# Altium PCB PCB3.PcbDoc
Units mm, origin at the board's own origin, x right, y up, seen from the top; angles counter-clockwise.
Board outline 98.68 x 60.83 mm, 2 copper layers (Top Layer, Bottom Layer); 30 components, 23 nets, 144 pads, 7 vias.
Unrouted connection lines stored in the file: 1.
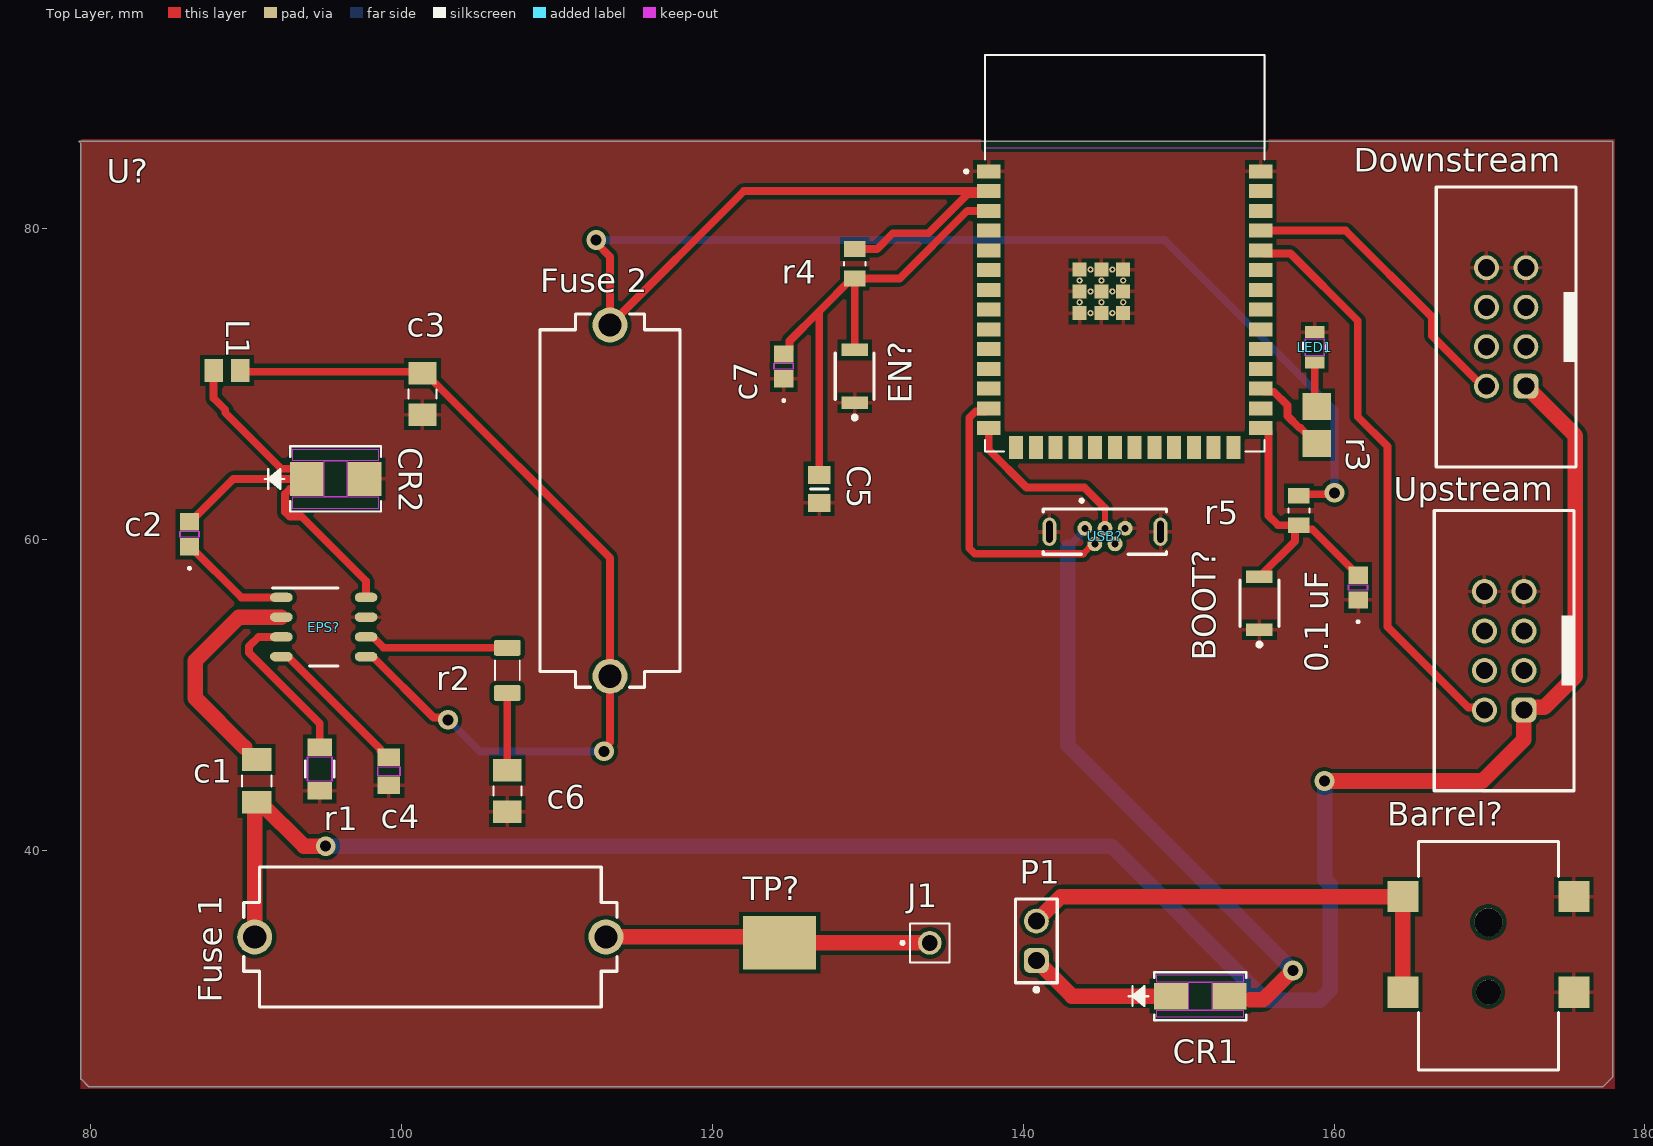
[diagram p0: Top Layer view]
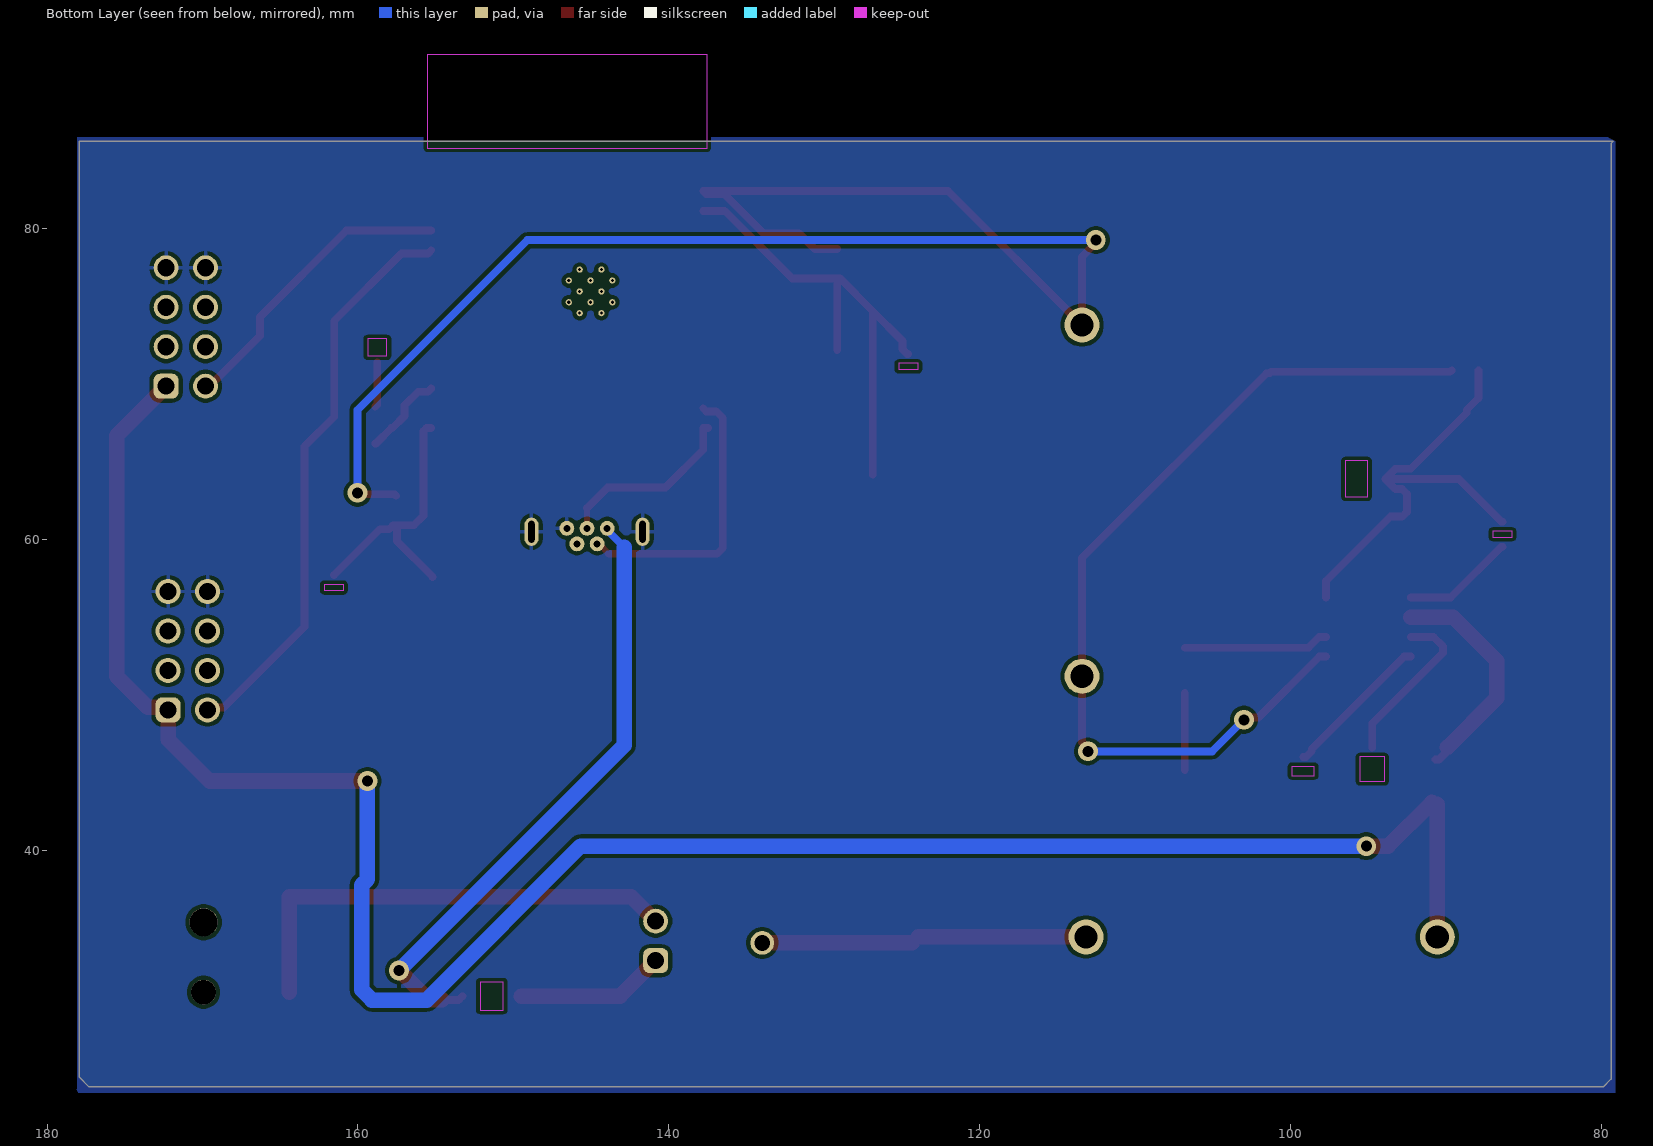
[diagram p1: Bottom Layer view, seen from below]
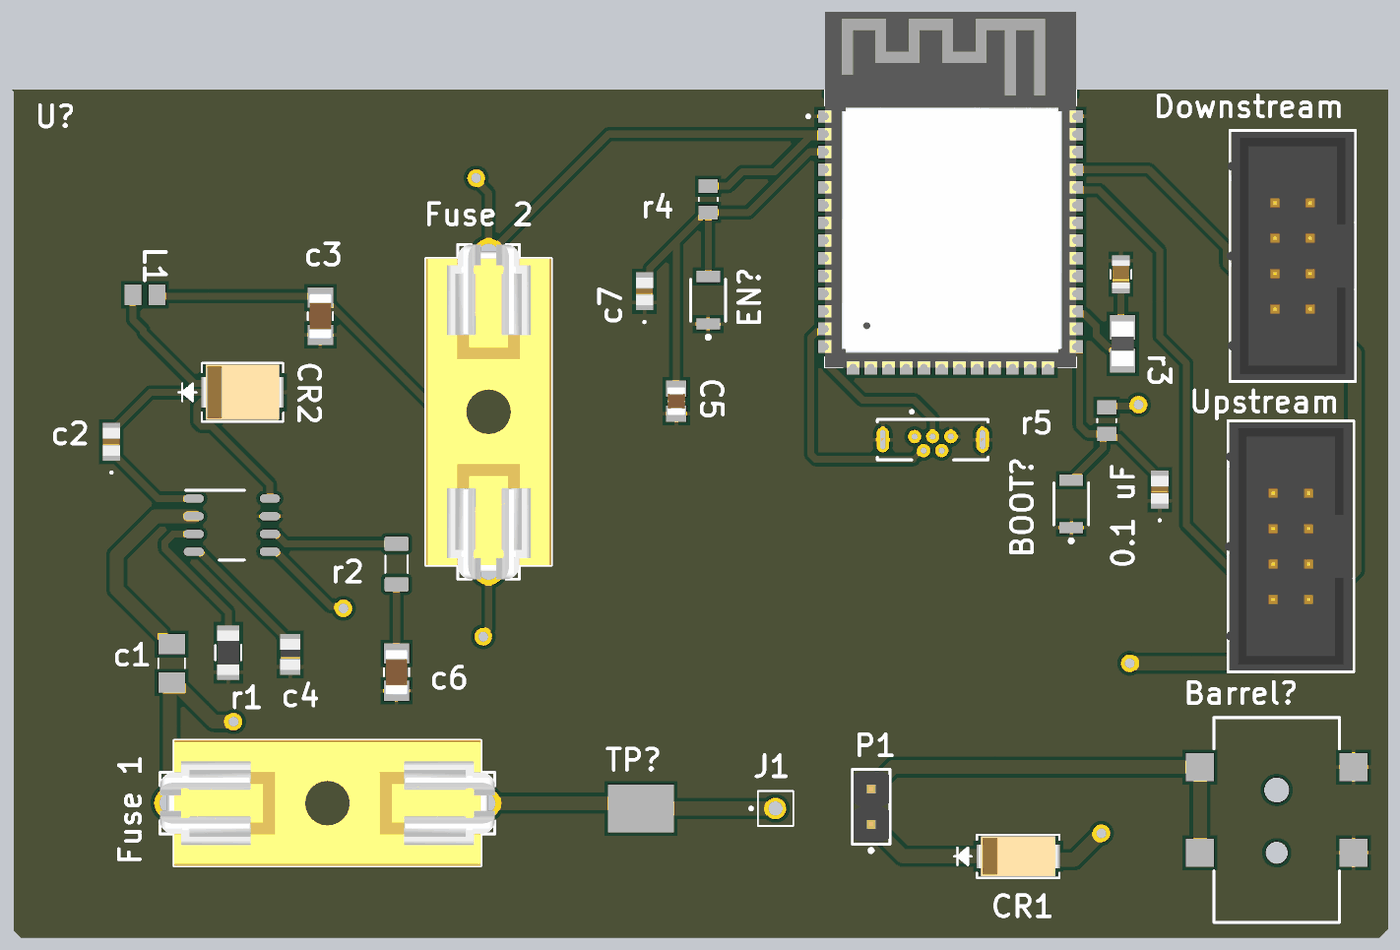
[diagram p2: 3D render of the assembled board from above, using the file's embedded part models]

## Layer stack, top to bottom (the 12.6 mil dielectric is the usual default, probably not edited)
Top Solder: solder mask 0.0102, Solder Resist, Dk 3.5
Top Layer: signal copper 0.0356
Dielectric 1: dielectric 0.32, FR-4, Dk 4.8
Bottom Layer: signal copper 0.0356
Bottom Solder: solder mask 0.0102, Solder Resist, Dk 3.5

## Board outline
79.375,25.273 79.883,24.765 177.292,24.765 177.927,25.4 177.927,85.598 79.248,85.598 79.375,85.471

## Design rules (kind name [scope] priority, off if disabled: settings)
Clearance [All] p1: gap=0.254 ignorepadtopadclearanceinfootprint=TRUE
MinimumSolderMaskSliver [All] p1: minsoldermaskwidth=0.1
PolygonConnect [All] p1: connectstyle=Relief reliefconductorwidth=0.254 reliefentries=4 polygonreliefangle="90 Angle" airgapwidth=0.254
RoutingVias [All] p1: holewidth=0.711 width=1.27 viastyle="Through Hole" minholewidth=0.711 minwidth=1.27 maxholewidth=0.711 maxwidth=1.27
SilkToSolderMaskClearance [IsText] p1: minsilkscreentomaskgap=0.254 clearancetoexposedcopper=TRUE
SolderMaskExpansion [All] p1: expansion=0.05 istentingtop=FALSE
SupplyNets "Schematic Supply Nets" [InNet('GND')] p1: voltage=0.000
Width [All] p1: maxlimit=1 minlimit=0.254 preferedwidth=0.5 minimp=50.000000 maximp=50.000000 favimp=50.000000
28 further rules are at their usual default settings.

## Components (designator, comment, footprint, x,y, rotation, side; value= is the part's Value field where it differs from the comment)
"0.1 uF" "KGM21NR71H104KT" CAP_KGM21_KAV 161.544,56.896 r90 top
Barrel? "DCJ200-05-A-XX-X_REVA" GCT_DCJ200-05-A-XX-X_REVA 169.926,33.211 r0 top
BOOT? "B3U-1000P" OMRON-B3U-1000_V 155.194,55.88 r90 top
c1 "GRJ31CR61E106KE11L" CAPC3216X190N 90.678,44.45 r90 top value=10µF
c2 "KGM21NR71H104KT" CAP_KGM21_KAV 86.36,60.325 r90 top
c3 "C3216X7S0J336M160AC" CAPC3216X180N 101.346,69.342 r90 top value=33µF
c4 "08055C103KAT2A" CAP_X7R_0805_AVX 99.187,45.085 r90 top
C5 "CL21B105KBFNNNE" CAPC2012X140N 126.873,63.246 r270 top value=1µF
c6 "C3216C0G2J222J115AA" CAPC3216X130N 106.807,43.815 r90 top value=2.2nF
c7 "KGM21NR71H104KT" CAP_KGM21_KAV 124.587,71.12 r90 top
CR1 "S1MTR" SMA_SDS 151.384,30.607 r0 top
CR2 "B240-13-F" SMB_DIO 95.758,63.881 r0 top
Downstream "61200821621" 61200821621 171.069,73.66 r90 top
EN? "B3U-1000P" OMRON-B3U-1000_V 129.159,70.485 r90 top
EPS? "TPS5403DR" D0008A_N 94.996,54.356 r0 top
"Fuse 1" "696101000002" 696101000002 101.854,34.417 r180 top
"Fuse 2" "696101000002" 696101000002 113.411,62.484 r90 top
J1 "PH1-01-UA" ADAM-TECH_PH1-01-UA 133.985,34.036 r0 top
L1 "MLF2012C820MT000" INDC2012X145N 88.773,70.866 r0 top value=82µH
LED1 "LSM0805452V" LED_05452V_VCC 158.75,72.352 r90 top
P1 "61300211121" 61300211121 140.843,34.163 r90 top
r1 "RC1206FR-0728KL" RC1206N_YAG 94.742,45.212 r270 top
r2 "RC1206FR-1047KL" RESC3116X65N 106.807,51.562 r90 top value=47k
r3 "HRG3216P-68R0-D-T1" RESC3216X55N 158.877,67.357 r270 top value=68
r4 "RMCF0805FT10K0" RESC2012X65N 129.159,77.724 r90 top value=10k
r5 "RMCF0805FT10K0" RESC2012X65N 157.734,61.849 r90 top value=10k
TP? "5018" TP470X343 124.333,34.036 r0 top
U? "ESP32-S3-WROOM-1-N8R8" XCVR_ESP32S3WROOM1N8R8 146.531,78.409 r0 top
Upstream "61200821621" 61200821621 170.942,52.832 r90 top
USB? "USB3131-30-0230-A_REVB" GCT_USB3131-30-0230-A_REVB 145.258,60.486 r0 top

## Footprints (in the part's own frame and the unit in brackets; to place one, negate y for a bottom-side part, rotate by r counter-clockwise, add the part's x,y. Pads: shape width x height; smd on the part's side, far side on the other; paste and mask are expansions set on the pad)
61200821621 [mm] "8 pins, straight, gold plating"
  rrect50% 1.6x1.6 hole 1.1: 1(-3.81,-1.27)
  round 1.6 hole 1.1: 2(-3.81,1.27) 3(-1.27,-1.27) 4(-1.27,1.27) 5(1.27,-1.27) 6(1.27,1.27) 7(3.81,-1.27) 8(3.81,1.27)
  silkscreen extent -9.01,-4.5 9.01,4.5, body extent -8.91,-4.42 8.91,4.75, height 9.13
61300211121 [mm] "Pin Header, pitch 2.54 mm, THT, Vertical, single row, 2p"
  rrect50% 1.6x1.6 hole 1.1: 1(-1.27,0)
  round 1.6 hole 1.1: 2(1.27,0)
  silkscreen extent -3.26,-1.35 2.69,1.35, body extent -2.54,-1.27 2.54,1.27, height 8.57
696101000002 [mm] "FUSEHOLDER BLOCKS - PCB - CLIP COVER - THT"
  round 2.25 hole 1.5: 1(-11.3,0) 2(11.3,0)
  silkscreen extent -12,-4.5 12,4.5, body extent -12,-4.5 12,4.5, height 13.55
ADAM-TECH_PH1-01-UA [mm]
  round 1.53 hole 1.02: 1(0,0)
  silkscreen extent -1.85,-1.25 1.27,1.25
CAP_KGM21_KAV [mil]
  rect 44x49 smd paste+0 mask+0: 1(-31.5,0) 2(31.5,0)
  Top Layer keep-out region: -7.5,-22.5 -7.5,22.5 7.5,22.5 7.5,-22.5
  Keep-Out Layer region: -7.5,-24.5 -7.5,24.5 7.5,24.5 7.5,-24.5
  silkscreen extent -89,-3 -84,3, body extent -39,-24 39,24, height 39
CAP_X7R_0805_AVX [mil]
  rect 44x57 smd paste+0 mask+0: 1(-35.5,0) 2(35.5,0)
  Top Layer keep-out region: -11.5,-26.5 -11.5,26.5 11.5,26.5 11.5,-26.5
  Keep-Out Layer region: -11.5,-28.5 -11.5,28.5 11.5,28.5 11.5,-28.5
  body extent -44,-29 44,29, height 37
CAPC2012X140N [mm]
  rect 1.15x1.45 smd: 1(-0.9,0) 2(0.9,0)
  silkscreen extent 0,-0.55 0,0.55, body extent -1,-0.63 1,0.63, height 1.35
CAPC3216X130N [mm]
  rect 1.44x1.82 smd: 1(-1.336,0) 2(1.336,0)
  silkscreen extent -0.29,-0.9 0.29,0.9, body extent -1.6,-0.8 1.6,0.8, height 1.3
CAPC3216X180N [mm]
  rect 1.44x1.82 smd: 1(-1.336,0) 2(1.336,0)
  silkscreen extent -0.29,-0.9 0.29,0.9, body extent -1.6,-0.8 1.6,0.8, height 1.8
CAPC3216X190N [mm]
  rect 1.45x1.91 smd: 1(-1.382,0) 2(1.382,0)
  silkscreen extent -0.34,-0.95 0.34,0.95
D0008A_N [mm]
  oval 1.45x0.6 smd paste+0 mask+0.051: 1(-2.725,1.905) 2(-2.725,0.635) 3(-2.725,-0.635) 4(-2.725,-1.905) 5(2.725,-1.905) 6(2.725,-0.635) 7(2.725,0.635) 8(2.725,1.905)
  silkscreen extent -3.3,-2.5 0.9,2.5
GCT_DCJ200-05-A-XX-X_REVA [mm]
  rect 2x2 smd: 1.1(-5.5,3.8) 1.2(-5.5,-2.35) 2(5.5,-2.35) 3(5.5,3.8)
  round 1.6 hole 1.6 unplated: ""(0,-2.35)
  round 1.8 hole 1.8 unplated: ""(0,2.15)
  silkscreen extent -4.5,-7.35 4.5,7.35
GCT_USB3131-30-0230-A_REVB [mm]
  round 0.958 hole 0.45: 1(-1.3,0.22) 2(-0.65,-0.78) 3(0,0.22) 4(0.65,-0.78) 5(1.3,0.22)
  oval 0.908x1.816 hole 0.4 slot 1.4 at 90 deg: S1(-3.575,0) S2(3.575,0)
  silkscreen extent -3.97,-1.45 3.97,2.1
INDC2012X145N [mm]
  rect 1.2x1.47 smd: 1(-0.86,0) 2(0.86,0)
LED_05452V_VCC [mil]
  rect 30x49 smd paste+0 mask+0: 1(-38.5,0) 2(38.5,0)
  Top Layer keep-out region: -21.5,-22.5 -21.5,22.5 21.5,22.5 21.5,-22.5
  Keep-Out Layer region: -21.5,-24.5 -21.5,24.5 21.5,24.5 21.5,-24.5
  silkscreen extent -11,-30 11,30, body extent -39,-24 39,24, height 43
OMRON-B3U-1000_V [mm] "SMD, 2-Leads, Body 3x2.5mm"
  rect 0.8x1.7 smd: 1(-1.7,0) 2(1.7,0)
  silkscreen extent -2.77,-1.25 1.5,1.25, body extent -1.5,-1.25 1.5,1.25, height 1.75
RC1206N_YAG [mil]
  rect 44x63 smd paste+0 mask+0: 1(-55,0) 2(55,0)
  Top Layer keep-out region: -31,-29.5 -31,29.5 31,29.5 31,-29.5
  Keep-Out Layer region: -31,-31.5 -31,31.5 31,31.5 31,-31.5
  silkscreen extent -21,-37 21,37, body extent -63,-31 63,31, height 28
RESC2012X65N [mm]
  rect 1.01x1.38 smd: 1(-0.95,0) 2(0.95,0)
  silkscreen extent -0.12,-0.68 0.12,0.68
RESC3116X65N [mm]
  rrect25% 1.02x1.73 smd: 1(-1.455,0) 2(1.455,0)
  silkscreen extent -0.63,-0.8 0.63,0.8
RESC3216X55N [mm]
  rect 1.74x1.82 smd: 1(-1.19,0) 2(1.19,0)
  body extent -1.6,-0.8 1.6,0.8, height 0.55
SMA_SDS [mil]
  rect 86x67 smd paste+0 mask+0: 1(-74.5,0) 2(74.5,0)
  Top Layer keep-out region: -109.5,-54 -109.5,-35.5 109.5,-35.5 109.5,-54
  Top Layer keep-out region: -109.5,35.5 -109.5,54 109.5,54 109.5,35.5
  Top Layer keep-out region: -29.5,-35.5 -29.5,35.5 29.5,35.5 29.5,-35.5
  Keep-Out Layer region: -29.5,-35.5 -29.5,35.5 29.5,35.5 29.5,-35.5
  silkscreen extent -182,-61 116,61, body extent -111,-56 111,56, height 118
SMB_DIO [mm]
  rect 2.18x2.21 smd paste+0 mask+0: 1(-1.857,0) 2(1.857,0)
  Top Layer keep-out region: -0.716,-1.156 -0.716,1.156 0.716,1.156 0.716,-1.156
  Top Layer keep-out region: -2.744,1.156 -2.744,1.919 2.744,1.919 2.744,1.156
  Top Layer keep-out region: -2.744,-1.919 -2.744,-1.156 2.744,-1.156 2.744,-1.919
  Keep-Out Layer region: -0.716,-1.156 -0.716,1.156 0.716,1.156 0.716,-1.156
  silkscreen extent -4.57,-2.1 2.92,2.1, body extent -2.8,-1.97 2.8,1.97, height 2.45
TP470X343 [mm]
  rect 4.7x3.43 smd: TP(0,0)
XCVR_ESP32S3WROOM1N8R8 [mm]
  rect 1.5x0.9 smd: 1(-8.75,5.26) 2(-8.75,3.99) 3(-8.75,2.72) 4(-8.75,1.45) 5(-8.75,0.18) 6(-8.75,-1.09) 7(-8.75,-2.36) 8(-8.75,-3.63) 9(-8.75,-4.9) 10(-8.75,-6.17) 11(-8.75,-7.44) 12(-8.75,-8.71) 13(-8.75,-9.98) 14(-8.75,-11.25) 27(8.75,-11.25) 28(8.75,-9.98) 29(8.75,-8.71) 30(8.75,-7.44) 31(8.75,-6.17) 32(8.75,-4.9) 33(8.75,-3.63) 34(8.75,-2.36) 35(8.75,-1.09) 36(8.75,0.18) 37(8.75,1.45) 38(8.75,2.72) 39(8.75,3.99) 40(8.75,5.26)
  rect 0.9x1.5 smd: 15(-6.985,-12.5) 16(-5.715,-12.5) 17(-4.445,-12.5) 18(-3.175,-12.5) 19(-1.905,-12.5) 20(-0.635,-12.5) 21(0.635,-12.5) 22(1.905,-12.5) 23(3.175,-12.5) 24(4.445,-12.5) 25(5.715,-12.5) 26(6.985,-12.5)
  rect 0.9x0.9 smd: 41_1(-1.5,-2.46) 41_2(-2.9,-2.46) 41_3(-0.1,-2.46) 41_4(-2.9,-3.86) 41_5(-1.5,-3.86) 41_6(-0.1,-3.86) 41_7(-2.9,-1.06) 41_8(-1.5,-1.06) 41_9(-0.1,-1.06)
  round 0.4 hole 0.2 mask+0: 41_10(-1.5,-1.76) 41_11(-2.9,-1.76) 41_12(-0.1,-1.76) 41_13(-2.9,-3.16) 41_14(-1.5,-3.16) 41_15(-0.1,-3.16) 41_16(-2.2,-1.06) 41_17(-0.8,-1.06) 41_18(-2.2,-2.46) 41_19(-0.8,-2.46) 41_20(-2.2,-3.86) 41_21(-0.8,-3.86)
  Keep-Out Layer region: 9,6.75 -9,6.75 -9,12.75 9,12.75
  Keep-Out Layer region: 9,6.75 -9,6.75 -9,12.75 9,12.75
  silkscreen extent -10.3,-12.75 9,12.75, body extent -9,-12.75 9,12.75, height 3.25

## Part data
"0.1 uF" c2 c7: library part CMP-001-00087-1, "No Description Available", Mfr_Name="KYOCERA AVX"
Barrel?: library part CMP-002-00092-1, "Power Barrel Connector Jack 2.05mm ID (0.081), 5.50mm OD (0.217) Surface Mount, Right Angle", Case/Package=None
BOOT? EN?: library part CMP-011-00000-2, "Tactile Switch, SPST-NO, 0.05 A, 12 V, -25 to 70 degC, 2-Pin SMD, RoHS, Tape and Reel", Case/Package=B3U-1000, Contact Current Rating=50mA, IP Rating=IP40, Manufacturer="Omron Electronic Components", Max Contact Resistance=100mohm, Max Operating Temperature=70°C, Max Voltage Rating (DC)=12V, Min Operating Temperature=-25°C, Operating Force=153gf, Package Description="2-Pin Surface Mount Device, Body 3 x 2.5 mm", Package Quantity=3500, Resistance=0.1Ohm
c1: library part CMP-001-00086-1, "CAP CER 10UF 25V X5R 1206", Case/Package=None
c3: library part CMP-001-00088-1, "33 ÂµF Â±20% 6.3V Ceramic Capacitor X7S 1206 (3216 Metric)", Case/Package="3216 TDK"
c4: library part CMP-001-00083-1, "No Description Available", Mfr_Name="KYOCERA AVX"
C5: library part CMP-001-00089-1, "1 ÂµF Â±10% 50V Ceramic Capacitor X7R 0805 (2012 Metric)", Case/Package="0805 Samsung"
c6: library part CMP-001-00085-1, "2200 pF Â±5% 630V Ceramic Capacitor C0G, NP0 1206 (3216 Metric)", Case/Package="3216 TDK"
CR1: library part CMP-084-000000-1, "No Description Available", Mfr_Name="SMC Diode Solutions"
CR2: library part CMP-047-000000-1, "No Description Available", Mfr_Name="Diodes Inc"
Downstream Upstream: library part CMP-002-00099-1, "WR-BHD Male Box Header, THT Straight, pitch 2.54mm, 2 row, 8 pin", Contact Resistance=20mOhm, Insulation Resistance=1000MOhm, Manufacturer="Wurth Elektronik", Operating Temperature Max=105°C, Operating Temperature Min=-40°C, Rated Current=3A, Withstanding Voltage=500V, Working Voltage=250V
EPS?: library part CMP-011-000000-1, "No Description Available", Mfr_Name="Texas Instruments"
"Fuse 1" "Fuse 2": library part CMP-040-000000-1, "WR-FSH Fuseholder THT Blocks PCB Clip Cover", Manufacturer="Wurth Elektronik", Operating Temperature Max=120°C, Operating Temperature Min=-30°C
J1: library part CMP-002-00312-1, "Pin Header 1P .100 Pitch Plug", Case/Package=None
L1: library part CMP-006-00021-1, "27 NH 3% LQW1005A27NH00", Case/Package=None
LED1: library part CMP-007-00036-1, "No Description Available", Mfr_Name=VCC
P1: library part CMP-002-00446-1, "WR-PHD Pin Header, THT, Vertical, pitch 2.54mm, 1 Row, 2P", Contact Resistance=20mOhm, Manufacturer="Wurth Elektronik", Operating Temperature Max=105°C, Operating Temperature Min=-40°C, Rated Current=3A, Withstanding Voltage=500V, Working Voltage=250V
r1: library part CMP-009-00179-1, "No Description Available", Mfr_Name=Yageo
r2: library part CMP-009-00180-1, Case/Package=None
r3: library part CMP-009-00182-1, "RES SMD 68 OHM 0.5% 1W 1206", Case/Package="3216 Susumu"
r4 r5: library part CMP-009-00181-1, Case/Package=None
TP?: library part CMP-013-000000-1, Package=None
U?: library part CMP-005-000000-1, "Bluetooth, WiFi 802.11b/g/n, Bluetooth v5.0 Transceiver Module 2.4GHz PCB Trace Surface Mount", Package=None
USB?: library part CMP-002-00073-1, "USB - micro B USB 2.0 Receptacle Connector 5 Position Through Hole", Case/Package=None

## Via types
v1: diameter 1.27, hole 0.711, Top Layer to Bottom Layer, 7 vias

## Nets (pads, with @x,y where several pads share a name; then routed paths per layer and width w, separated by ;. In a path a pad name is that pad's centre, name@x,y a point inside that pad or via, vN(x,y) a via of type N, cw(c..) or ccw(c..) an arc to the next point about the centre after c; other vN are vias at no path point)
GND: "0.1 uF.1" Barrel?.2 Barrel?.3 BOOT?.1 c3.1 c4.1 C5.2 c6.1 c7.1 CR2.2 Downstream.7 Downstream.8 EN?.1 EPS?.7 LED1.2 r1.2 U?.1 U?.40 U?.41_1 U?.41_2 U?.41_3 U?.41_4 U?.41_5 U?.41_6 U?.41_7 U?.41_8 U?.41_9 Upstream.7 Upstream.8 USB?.5 USB?.S1 USB?.S2
"Net0.1 uF_2": "0.1 uF.2" BOOT?.2 r5.1 U?.27 | length 17.7
  Top Layer w0.5: BOOT?.2 157.484,59.87 157.484,60.649 r5.1 ; U?.27 155.581,67.159 155.781,66.959 155.781,61.516 156.398,60.899 r5.1 ; 161.544,57.696 158.591,60.649 157.984,60.649 r5.1
NetBarrel?_1.1: Barrel?.1.1 Barrel?.1.2 P1.2 | length 30.4
  Top Layer w1: P1.2 142.421,37.011 Barrel?.1.1 Barrel?.1.2
Netc1_1: "Fuse 1.2" c1.1 Downstream.1 Upstream.1 | length 136.9
  Top Layer w0.5: c1.1@90.554,42.944 c1.1 c1.1@90.908,43.068
  Top Layer w1: 90.554,34.417 c1.1@90.554,42.944 ; c1.1@90.908,43.068 93.717,40.259 v1(95.123,40.259) ; v1(159.385,44.45) 169.545,44.45 172.212,47.117 Upstream.1 172.384,49.194 173.527,49.194 175.514,51.181 175.514,66.675 Downstream.1
  Bottom Layer w1: v1(95.123,40.259) 145.669,40.259 155.571,30.357 159.095,30.357 159.762,31.024 159.762,37.746 159.385,38.123 v1(159.385,44.45)
Netc1_2: c1.2 EPS?.2 | length 14.8
  Top Layer w0.5: 89.898,46.612 89.898,46.382 90.448,45.832 c1.2
  Top Layer w1: 89.898,46.612 86.741,49.769 86.741,52.197 89.535,54.991 EPS?.2
Netc2_1: c2.1 EPS?.1 | length 7.3
  Top Layer w0.5: c2.1 86.423,59.525 89.687,56.261 EPS?.1
Netc2_2: c2.2 CR2.1 EPS?.8 L1.1 | length 29.8
  Top Layer w0.5: c2.2 86.423,61.125 89.179,63.881 CR2.1 ; L1.1 87.913,69.08 88.656,68.337 88.656,68.144 92.267,64.533 93.249,64.533 CR2.1 ; EPS?.8 97.721,57.311 93.574,61.458 92.805,61.458 92.51,61.753 92.51,62.934 92.805,63.229 93.249,63.229 CR2.1
Netc3_2: "Fuse 2.1" c3.2 EPS?.5 L1.2 | length 59.2
  Top Layer w0.5: L1.2 89.727,70.772 101.252,70.772 c3.2 101.536,70.678 113.411,58.803 113.411,51.184 113.411,46.944 113.03,46.563 v1(113.03,46.355) ; EPS?.5 98.146,52.451 102.063,48.534 102.85,48.534 v1(102.997,48.387)
  Bottom Layer w0.5: v1(102.997,48.387) 105.029,46.355 v1(113.03,46.355)
Netc4_2: c4.2 EPS?.4 | length 9.7
  Top Layer w0.5: EPS?.4 92.696,52.451 98.638,46.509 98.638,46.37 99.022,45.987 c4.2
NetC5_1: C5.1 c7.2 EN?.2 r4.1 U?.3 | length 32.4
  Top Layer w0.5: c7.2 124.65,71.92 124.959,72.229 124.959,72.759 126.873,74.673 ; C5.1 126.873,74.673 ; EN?.2 r4.1 ; U?.3 136.406,81.129 132.051,76.774 r4.1 ; 126.873,74.673 128.974,76.774 r4.1
Netc6_2: c6.2 r2.1 | length 5
  Top Layer w0.5: c6.2 r2.1
NetCR1_1: CR1.1 P1.1 | length 9.6
  Top Layer w1: P1.1 143.129,30.607 CR1.1
NetCR1_2: CR1.2 USB?.1 | length 39.9
  Top Layer w0.5: CR1.2 153.519,30.364 154.573,30.364
  Top Layer w1: 154.573,30.364 155.418,30.364 157.312,32.258 v1(157.353,32.258)
  Bottom Layer w0.5: 142.875,59.499 143.958,60.582 USB?.1
  Bottom Layer w1: 142.875,59.499 142.875,46.736 v1(157.353,32.258)
NetDownstream_2: Downstream.2 U?.37 | length 18.5
  Top Layer w0.5: U?.37 160.744,79.859 166.299,74.304 166.299,73.096 169.094,70.301
NetEPS?_3: EPS?.3 r1.1 | length 10.7
  Top Layer w0.5: EPS?.3 90.805,53.721 90.193,53.109 90.193,52.695 94.742,48.146 r1.1
NetEPS?_6: EPS?.6 r2.2 | length 9.4
  Top Layer w0.5: EPS?.6 98.146,53.721 98.85,53.017 r2.2
"NetFuse 1_1": "Fuse 1.1" J1.1 TP?.TP | length 21
  Top Layer w0.5: TP?.TP@123.952,34.417 TP?.TP
  Top Layer w1: 113.154,34.417 TP?.TP@123.952,34.417 ; TP?.TP J1.1
"NetFuse 2_2": "Fuse 2.2" r4.2 r5.2 U?.2 | length 103.8
  Top Layer w0.5: v1(112.522,79.248) 112.522,79.067 113.411,78.178 113.411,73.784 122.026,82.399 U?.2 137.581,82.199 136.41,82.199 133.901,79.69 131.615,79.69 130.599,78.674 r4.2 ; r5.2@157.549,62.799 157.645,62.896 159.924,62.896 v1(160.02,62.992)
  Bottom Layer w0.5: v1(112.522,79.248) 149.098,79.248 160.02,68.326 v1(160.02,62.992)
NetLED1_1: LED1.1 r3.1 | length 2.9
  Top Layer w0.5: LED1.1 158.75,68.674 r3.1
Netr3_2: r3.2 U?.29 | length 5.5
  Top Layer w0.5: U?.29 155.481,69.499 156.124,69.499 156.999,68.624 156.999,67.932 157.758,67.173 157.831,67.173 158.837,66.167 r3.2
NetU?_13: U?.13 USB?.2 | length 18.4
  Top Layer w0.385: 143.852,59.074 USB?.2@144.484,59.706
  Top Layer w0.5: U?.13 137.581,68.229 136.938,68.229 136.527,67.818 136.527,59.434 136.887,59.074 143.852,59.074 ; USB?.2@144.484,59.706 USB?.2
NetU?_14: U?.14 USB?.3 | length 12
  Top Layer w0.385: USB?.3 145.258,62.006
  Top Layer w0.5: U?.14@137.481,67.159 U?.14 137.781,65.761 140.211,63.331 143.933,63.331 145.258,62.006
NetU?_36: U?.36 Upstream.2 | length 37.1
  Top Layer w0.5: U?.36 155.481,78.389 157.196,78.389 161.527,74.058 161.527,67.882 163.432,65.977 163.432,54.373 168.631,49.174 169.52,49.174 Upstream.2
pads on no net: Barrel?. Downstream.3 Downstream.4 Downstream.5 Downstream.6 U?.4 U?.5 U?.6 U?.7 U?.8 U?.9 U?.10 U?.11 U?.12 U?.15 U?.16 U?.17 U?.18 U?.19 U?.20 U?.21 U?.22 U?.23 U?.24 U?.25 U?.26 U?.28 U?.30 U?.31 U?.32 U?.33 U?.34 U?.35 U?.38 U?.39 U?.41_10 U?.41_11 U?.41_12 U?.41_13 U?.41_14 U?.41_15 U?.41_16 U?.41_17 U?.41_18 U?.41_19 U?.41_20 U?.41_21 Upstream.3 Upstream.4 Upstream.5 Upstream.6 USB?.4

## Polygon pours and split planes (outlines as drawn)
GND on Top Layer "GND_L01_P000" (solid, pour order 0): 178.054,85.725 178.054,24.638 79.375,24.638 79.375,85.598 79.248,85.725
GND on Bottom Layer "GND_L02_P001" (solid, pour order 1): 79.375,85.725 79.502,85.852 178.054,85.852 178.054,24.638 178.308,24.384 79.121,24.384 79.121,85.725 79.248,85.852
